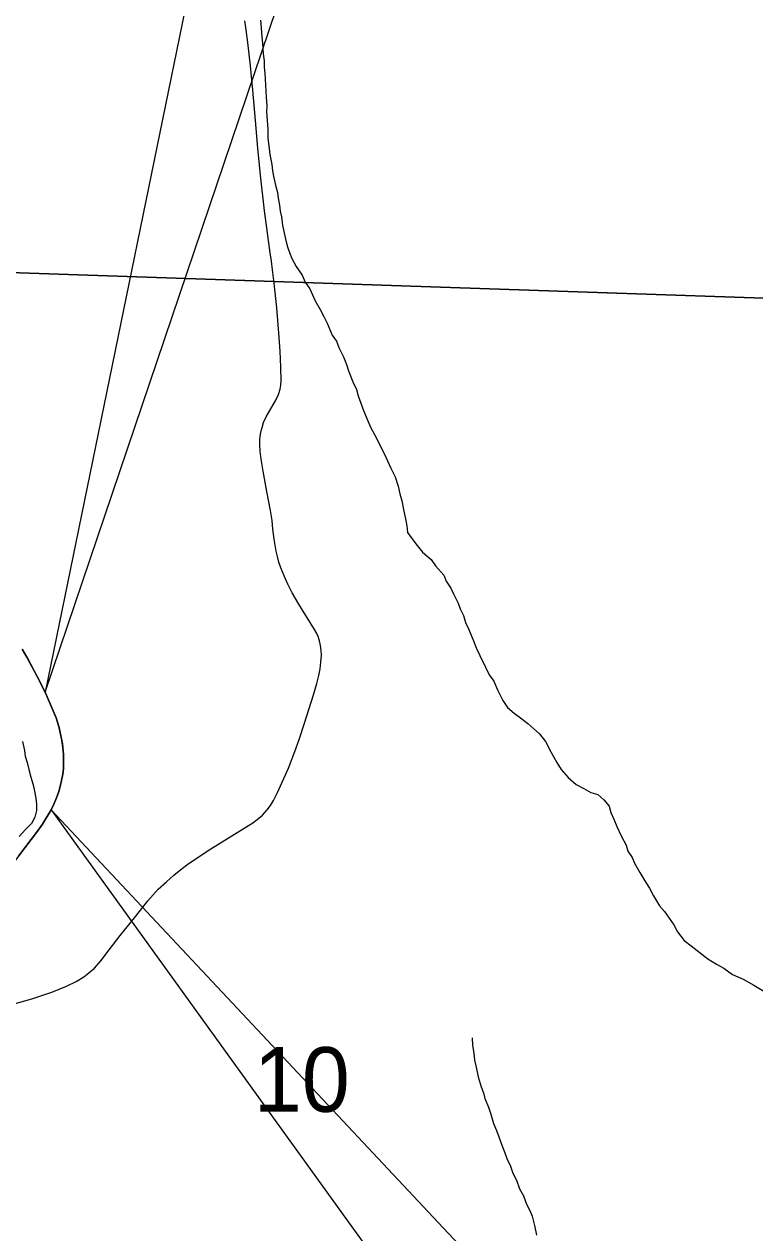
# Model space of a CAD drawing. Extents: x -3.3 to 34, y 0 to 56.8.
# Drawn here: x 0.004 to 0.477, y 31.042 to 31.825 of the extents above; entities that cross this region are included whole.
import ezdxf

# ---------------------------------------------------------------- set-up
doc = ezdxf.new("R2010")
doc.units = 0
for name, color, linetype in [('GM_X_Corporation', 7, 'Continuous'), ('GM_X_County_Road', 7, 'Continuous'), ('GM_X_Major_River', 7, 'Continuous'), ('GM_X_Section_Text', 7, 'Continuous'), ('GM_X_State_Route', 7, 'Continuous'), ('GM_X_Township_Road', 7, 'Continuous'), ('GT_Project_Soil_Layers', 7, 'Continuous'), ('SH_Major_Grid_Line', 7, 'Continuous')]:
    doc.layers.add(name, color=color, linetype=linetype)

msp = doc.modelspace()

# ---------------------------------------------------------------- linework, layer by layer
at = {"layer": 'GM_X_Corporation'}
for points in [[(-0.28775, 32.6826), (0.73569, 32.62424), (0.6926, 31.6401), (-0.3225, 31.67471)], [(-0.3225, 31.67471), (0.6926, 31.6401), (0.65935, 30.63337), (-0.36109, 30.66979)]]:
    msp.add_lwpolyline(points, close=True, dxfattribs=at)
at = {"layer": 'GM_X_County_Road'}
msp.add_lwpolyline([(0.00051, 31.2859), (0.01288, 31.30214), (0.016, 31.30658), (0.02177, 31.31596), (0.0237, 31.32), (0.02524, 31.32378), (0.02663, 31.32784), (0.02775, 31.33183), (0.02844, 31.33487), (0.02918, 31.33903), (0.0296, 31.34257), (0.02976, 31.34646), (0.02964, 31.35182), (0.02927, 31.35637), (0.02864, 31.36089), (0.02763, 31.36597), (0.02665, 31.36977), (0.02483, 31.37542), (0.02299, 31.38003), (0.01775, 31.39206), (0.01273, 31.40225), (0.00597, 31.41487), (0.00293, 31.42005)], dxfattribs=at)
at = {"layer": 'GM_X_Major_River'}
msp.add_lwpolyline([(0.00323, 31.36009), (0.00445, 31.35441), (0.00488, 31.35062), (0.00607, 31.34646), (0.00727, 31.34193), (0.00848, 31.33701), (0.01006, 31.3321), (0.01087, 31.32793), (0.01169, 31.32339), (0.01213, 31.3196), (0.01218, 31.31543), (0.0111, 31.31124), (0.00888, 31.30703), (0.00514, 31.30319), (0.00104, 31.29858)], dxfattribs=at)
at = {"layer": 'GM_X_State_Route'}
for points in [[(0.00293, 31.42005), (0.00597, 31.41487), (0.00655, 31.41379)], [(0.00655, 31.41379), (0.01273, 31.40225), (0.01775, 31.39206)], [(0.01775, 31.39206), (0.02299, 31.38003), (0.02483, 31.37542), (0.02665, 31.36977), (0.02763, 31.36597)], [(0.02763, 31.36597), (0.02895, 31.35867), (0.02927, 31.35637), (0.02964, 31.35182), (0.02976, 31.34646), (0.0296, 31.34257), (0.02918, 31.33903), (0.02844, 31.33487), (0.02775, 31.33183), (0.02663, 31.32784), (0.02524, 31.32378), (0.0237, 31.32), (0.02177, 31.31596)], [(0.02177, 31.31596), (0.016, 31.30658), (0.01288, 31.30214), (0.00051, 31.2859), (-0.01063, 31.27126), (-0.02164, 31.25654), (-0.0335, 31.23934), (-0.03638, 31.23479), (-0.05098, 31.21098), (-0.05526, 31.20399), (-0.06072, 31.19461), (-0.06351, 31.18946), (-0.06761, 31.18114), (-0.06881, 31.17768), (-0.07005, 31.17398), (-0.07095, 31.17119)]]:
    msp.add_lwpolyline(points, dxfattribs=at)
at = {"layer": 'GM_X_Township_Road'}
msp.add_lwpolyline([(-0.00132, 31.1905), (0.00986, 31.19363), (0.02218, 31.19782), (0.03156, 31.20168), (0.03799, 31.20483), (0.04285, 31.20783), (0.04608, 31.21028), (0.04971, 31.21339), (0.05394, 31.21804), (0.05932, 31.22533), (0.06639, 31.23453), (0.07651, 31.2471), (0.08438, 31.25687), (0.09104, 31.26443), (0.0963, 31.26937), (0.10107, 31.27356), (0.10665, 31.27808), (0.1111, 31.28145), (0.12513, 31.29063), (0.14504, 31.30291), (0.15236, 31.30759), (0.15511, 31.30964), (0.15847, 31.31255), (0.16161, 31.31599), (0.16368, 31.31867), (0.16565, 31.32199), (0.16832, 31.32706), (0.17532, 31.34294), (0.17947, 31.35371), (0.18228, 31.36152), (0.18574, 31.37204), (0.19148, 31.39035), (0.19371, 31.39769), (0.19503, 31.40295), (0.19585, 31.40731), (0.19633, 31.41154), (0.19667, 31.4161), (0.19654, 31.41919), (0.19612, 31.42237), (0.19547, 31.42525), (0.1945, 31.4282), (0.19372, 31.43012), (0.19223, 31.43275), (0.18656, 31.44184), (0.18208, 31.44904), (0.17786, 31.45636), (0.17497, 31.46205), (0.1725, 31.46738), (0.17039, 31.47261), (0.16921, 31.47627), (0.16823, 31.47997), (0.16746, 31.48337), (0.16617, 31.49115), (0.16535, 31.49773), (0.16477, 31.50323), (0.16382, 31.50976), (0.1614, 31.52206), (0.15902, 31.53529), (0.15762, 31.54302), (0.15705, 31.54811), (0.1568, 31.55231), (0.15688, 31.55584), (0.15729, 31.55922), (0.15771, 31.56135), (0.15823, 31.56356), (0.15927, 31.56673), (0.16091, 31.57039), (0.16721, 31.58118), (0.1689, 31.58478), (0.16994, 31.58826), (0.17042, 31.59095), (0.17064, 31.59363), (0.17052, 31.60253), (0.16989, 31.61287), (0.16928, 31.62182), (0.16773, 31.641), (0.16606, 31.65699), (0.16502, 31.66566), (0.16435, 31.6712), (0.1635, 31.67663), (0.16148, 31.69099), (0.15984, 31.70389), (0.15729, 31.72699), (0.15555, 31.74432), (0.15396, 31.76223), (0.15221, 31.78204), (0.15083, 31.79764), (0.14913, 31.81274), (0.14803, 31.82111), (0.14712, 31.82692)], dxfattribs=at)
at = {"layer": 'GT_Project_Soil_Layers'}
for points in [[(0.15728, 31.82719), (0.15772, 31.82226), (0.15818, 31.81657), (0.15862, 31.8124), (0.15909, 31.80557), (0.15953, 31.80102), (0.15959, 31.79685), (0.16002, 31.79306), (0.16099, 31.77751), (0.16145, 31.77182), (0.16112, 31.76802), (0.16203, 31.75664), (0.16211, 31.75095), (0.16296, 31.74413), (0.16339, 31.74034), (0.16462, 31.7339), (0.16505, 31.72973), (0.16587, 31.72519), (0.16709, 31.71951), (0.16828, 31.71573), (0.16871, 31.71194), (0.16953, 31.70739), (0.16996, 31.7036), (0.17077, 31.69982), (0.1716, 31.69452), (0.17242, 31.69035), (0.17363, 31.68467), (0.17483, 31.68052), (0.17602, 31.67674), (0.17758, 31.67296), (0.18031, 31.66768), (0.18418, 31.66204), (0.18614, 31.65752), (0.18923, 31.65338), (0.19275, 31.64546), (0.19586, 31.63981), (0.1982, 31.63528), (0.20053, 31.63114), (0.20367, 31.62321), (0.20638, 31.61946), (0.20795, 31.6153), (0.21107, 31.60927), (0.21303, 31.60436), (0.21422, 31.60021), (0.21698, 31.59303), (0.21932, 31.58813), (0.22051, 31.58397), (0.22405, 31.57453), (0.2268, 31.56773), (0.22876, 31.56321), (0.23109, 31.55906), (0.23615, 31.54926), (0.23849, 31.54436), (0.24163, 31.53719), (0.24436, 31.53154), (0.24634, 31.52549), (0.24754, 31.52057), (0.24874, 31.51604), (0.24997, 31.50922), (0.25118, 31.5043), (0.252, 31.49976), (0.25243, 31.49559), (0.25784, 31.48807), (0.26208, 31.48282), (0.26784, 31.47796), (0.27055, 31.47382), (0.27594, 31.46783), (0.27751, 31.46405), (0.2806, 31.45954), (0.28217, 31.45577), (0.28529, 31.44974), (0.28648, 31.44596), (0.28881, 31.44182), (0.29001, 31.43728), (0.29196, 31.43313), (0.29471, 31.42633), (0.29706, 31.42029), (0.2994, 31.41577), (0.30292, 31.40823), (0.30526, 31.40333), (0.30835, 31.3992), (0.3107, 31.39353), (0.3142, 31.38675), (0.3173, 31.38224), (0.32152, 31.3785), (0.3265, 31.37478), (0.33033, 31.37179), (0.33417, 31.36843)], [(0.33417, 31.36843), (0.33801, 31.36507), (0.34187, 31.36018), (0.34537, 31.3534), (0.34926, 31.34662), (0.35198, 31.34211), (0.3566, 31.33686), (0.36159, 31.33237), (0.36655, 31.32978), (0.37114, 31.32719), (0.37571, 31.32573), (0.37954, 31.32237), (0.38301, 31.31824), (0.38421, 31.31408), (0.38616, 31.30994), (0.38812, 31.30503), (0.39086, 31.299), (0.39398, 31.29296), (0.39516, 31.28919), (0.39787, 31.28505), (0.39944, 31.28128), (0.40294, 31.27525), (0.40681, 31.26885), (0.40914, 31.26509), (0.41186, 31.26019), (0.41574, 31.2538), (0.41883, 31.25004), (0.42501, 31.2414), (0.42735, 31.23688), (0.43159, 31.23124), (0.43619, 31.22789), (0.44692, 31.21931), (0.45266, 31.21597), (0.45724, 31.21338), (0.46299, 31.20928), (0.46985, 31.20634), (0.47673, 31.20226), (0.48323, 31.19856)], [(0.29442, 31.16826), (0.29448, 31.16333), (0.29531, 31.15841), (0.29575, 31.15386), (0.29695, 31.14932), (0.29817, 31.14289), (0.30016, 31.13647), (0.30172, 31.13269), (0.30253, 31.12891), (0.30489, 31.12325), (0.30646, 31.11872), (0.30806, 31.11267), (0.31002, 31.10814), (0.31395, 31.09757), (0.31552, 31.0938), (0.31671, 31.09002), (0.31905, 31.08512), (0.32063, 31.08058), (0.32297, 31.07606), (0.32494, 31.0704), (0.32766, 31.06588), (0.32962, 31.0606), (0.33158, 31.05645), (0.33314, 31.05267), (0.33474, 31.04663), (0.33596, 31.04057)]]:
    msp.add_lwpolyline(points, dxfattribs=at)
at = {"layer": 'SH_Major_Grid_Line'}
for points in [[(0.01775, 31.39206), (0.40453, 32.53549), (0.25313, 32.54065)], [(0.02177, 31.31596), (0.75855, 30.29376), (0.75776, 30.531)]]:
    msp.add_lwpolyline(points, close=True, dxfattribs=at)

# ---------------------------------------------------------------- texts
at = {"layer": 'GM_X_Section_Text'}
msp.add_text('10', height=0.041856, rotation=0.00001, dxfattribs=at).set_placement((0.15285, 31.12036))

doc.saveas('drawing.dxf')
